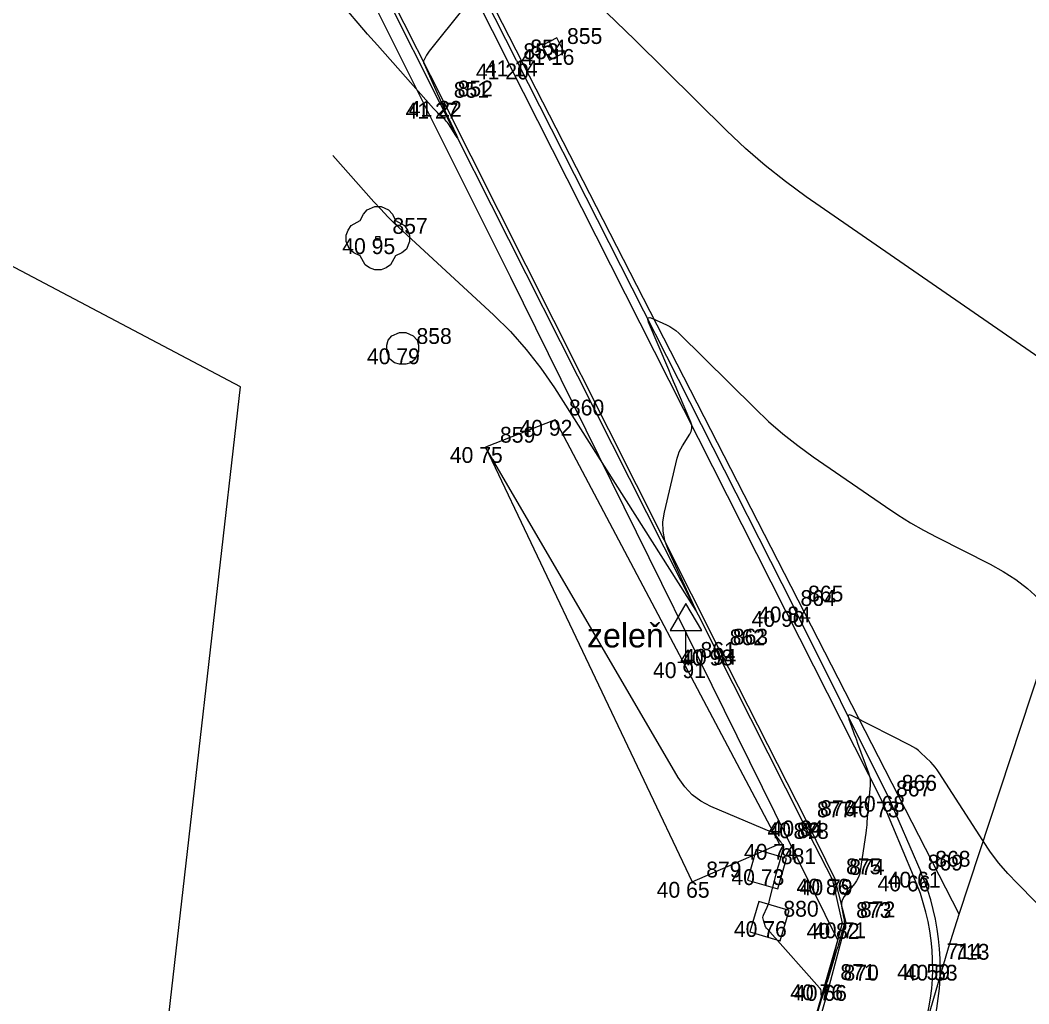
# Model space of a CAD drawing. Extents: x -702257 to -701487, y -1009871 to -1008841.
# Drawn here: x -701709.3 to -701693.36, y -1009123.07 to -1009107.52 of the extents above; entities that cross this region are included whole.
import ezdxf

# ---------------------------------------------------------------- set-up
doc = ezdxf.new("R2010")
doc.units = 0
for name, color, linetype in [('Ex_Major Contours', 7, 'Continuous'), ('Ex_Minor Contours', 7, 'Continuous'), ('Z_body', 7, 'Continuous'), ('Z_body_cisla', 7, 'Continuous'), ('Z_body_vysky_redukovane', 7, 'Continuous'), ('Z_dopravni_znacky', 7, 'Continuous'), ('Z_katastr_hranice', 7, 'Continuous'), ('Z_komunikace', 7, 'Continuous'), ('Z_obruba', 7, 'Continuous'), ('Z_popisy', 7, 'Continuous'), ('Z_site_kanalizace_znaky', 7, 'Continuous'), ('Z_site_nerozlisene_znaky', 7, 'Continuous'), ('Z_zelen_jednotliva', 7, 'Continuous'), ('Z_zelen_obvod', 7, 'Continuous')]:
    doc.layers.add(name, color=color, linetype=linetype)

# ---------------------------------------------------------------- blocks, each defined once
blk = doc.blocks.new('POINT_DISPLAY')
blk.add_line((0, 0), (0, 0))
blk = doc.blocks.new('Z620')
for p, q in [((-0.23, 0.13), (-0.17, 0.2)), ((-0.17, 0.2), (-0.05, 0.25)), ((-0.05, 0.25), (0.05, 0.25)), ((0.05, 0.25), (0.17, 0.2)), ((0.17, 0.2), (0.23, 0.13)), ((-0.25, 0.05), (-0.23, 0.13)), ((-0.25, -0.05), (-0.25, 0.05)), ((0.23, 0.13), (0.25, 0.05)), ((0.25, 0.05), (0.25, -0.05)), ((-0.2, -0.17), (-0.25, -0.05)), ((0.25, -0.05), (0.2, -0.17)), ((-0.13, -0.23), (-0.2, -0.17)), ((-0.05, -0.25), (-0.13, -0.23)), ((0.05, -0.25), (-0.05, -0.25)), ((0.13, -0.23), (0.05, -0.25)), ((0.2, -0.17), (0.13, -0.23))]:
    blk.add_line(p, q)
blk = doc.blocks.new('Z46260')
for p, q in [((0.13, 0.13), (-0.13, 0.13)), ((-0.13, 0.13), (-0.13, -0.13)), ((0.13, 0), (-0.13, 0)), ((0.13, -0.13), (0.13, 0.13)), ((-0.13, -0.13), (0.13, -0.13))]:
    blk.add_line(p, q)
blk = doc.blocks.new('Z24')
for p, q in [((-0.17, 0.45), (-0.05, 0.5)), ((-0.05, 0.5), (0.05, 0.5)), ((0.05, 0.5), (0.17, 0.45)), ((-0.28, 0.28), (-0.23, 0.38)), ((-0.23, 0.38), (-0.17, 0.45)), ((0.17, 0.45), (0.23, 0.38)), ((0.23, 0.38), (0.28, 0.28)), ((-0.47, 0.13), (-0.42, 0.2)), ((-0.42, 0.2), (-0.28, 0.28)), ((0.28, 0.28), (0.42, 0.2)), ((0.42, 0.2), (0.47, 0.13)), ((-0.5, 0.05), (-0.47, 0.13)), ((-0.5, -0.05), (-0.5, 0.05)), ((-0.03, -0.03), (-0.03, 0.03)), ((-0.03, 0.03), (0.03, 0.03)), ((0.03, 0.03), (0.03, -0.03)), ((0.47, 0.13), (0.5, 0.05)), ((0.5, 0.05), (0.5, -0.05)), ((-0.45, -0.17), (-0.5, -0.05)), ((0.03, -0.03), (-0.03, -0.03)), ((0.5, -0.05), (0.45, -0.17)), ((-0.38, -0.23), (-0.45, -0.17)), ((-0.28, -0.28), (-0.38, -0.23)), ((-0.2, -0.42), (-0.28, -0.28)), ((0.28, -0.28), (0.2, -0.42)), ((0.38, -0.23), (0.28, -0.28)), ((0.45, -0.17), (0.38, -0.23)), ((-0.13, -0.47), (-0.2, -0.42)), ((-0.05, -0.5), (-0.13, -0.47)), ((0.13, -0.47), (0.05, -0.5)), ((0.2, -0.42), (0.13, -0.47)), ((0.05, -0.5), (-0.05, -0.5))]:
    blk.add_line(p, q)
blk = doc.blocks.new('Z608')
for p, q in [((0.25, 0.25), (-0.25, 0.25)), ((-0.25, 0.25), (-0.25, -0.25)), ((0.25, -0.25), (0.25, 0.25)), ((-0.25, -0.25), (0.25, -0.25))]:
    blk.add_line(p, q)
blk = doc.blocks.new('Z527')
for p, q in [((0, 0.93), (-0.25, 0.5)), ((0.25, 0.5), (0, 0.93)), ((-0.25, 0.5), (0.25, 0.5)), ((0, 0), (0, 0.5)), ((-0.13, 0), (0.13, 0))]:
    blk.add_line(p, q)

msp = doc.modelspace()

# ---------------------------------------------------------------- linework, layer by layer
at = {"layer": 'Ex_Major Contours'}
msp.add_lwpolyline([(-701704.362, -1009109.662), (-701703.713, -1009110.392), (-701703.604, -1009110.513), (-701703.491, -1009110.63), (-701703.376, -1009110.745), (-701703.258, -1009110.856), (-701701.824, -1009112.18), (-701701.554, -1009112.445), (-701701.304, -1009112.726), (-701701.072, -1009113.023), (-701700.859, -1009113.335), (-701698.629, -1009116.845), (-701698.622, -1009116.856), (-701698.619, -1009116.859), (-701698.62, -1009116.854), (-701698.625, -1009116.842), (-701698.662, -1009116.763), (-701698.684, -1009116.716), (-701699.063, -1009115.89), (-701699.116, -1009115.746), (-701699.143, -1009115.599), (-701699.145, -1009115.45), (-701699.121, -1009115.298), (-701698.919, -1009114.447), (-701698.904, -1009114.395), (-701698.885, -1009114.345), (-701698.862, -1009114.297), (-701698.835, -1009114.25), (-701698.718, -1009114.068), (-701698.696, -1009114.022), (-701698.685, -1009113.975), (-701698.687, -1009113.926), (-701698.702, -1009113.877), (-701698.896, -1009113.42), (-701698.936, -1009113.328), (-701698.975, -1009113.235), (-701699.014, -1009113.142), (-701699.053, -1009113.049), (-701699.37, -1009112.298), (-701699.383, -1009112.252), (-701699.377, -1009112.227), (-701699.352, -1009112.222), (-701699.307, -1009112.237), (-701699.089, -1009112.336), (-701699.036, -1009112.362), (-701698.986, -1009112.394), (-701698.939, -1009112.429), (-701698.895, -1009112.469), (-701697.693, -1009113.657), (-701697.474, -1009113.864), (-701697.247, -1009114.06), (-701697.012, -1009114.247), (-701696.768, -1009114.424), (-701695.628, -1009115.211), (-701695.431, -1009115.342), (-701695.23, -1009115.467), (-701695.025, -1009115.584), (-701694.816, -1009115.694), (-701693.97, -1009116.121), (-701693.764, -1009116.235), (-701693.568, -1009116.363), (-701693.383, -1009116.506), (-701693.208, -1009116.664)], dxfattribs=at)
at = {"layer": 'Ex_Minor Contours'}
for points in [[(-701702.287, -1009107.325), (-701702.84, -1009108.014), (-701702.851, -1009108.029), (-701702.862, -1009108.045), (-701702.872, -1009108.06), (-701702.881, -1009108.077), (-701702.926, -1009108.159), (-701702.93, -1009108.167), (-701702.931, -1009108.176), (-701702.931, -1009108.184), (-701702.928, -1009108.193), (-701702.897, -1009108.262), (-701702.714, -1009108.675), (-701702.682, -1009108.746), (-701702.649, -1009108.818), (-701702.617, -1009108.889), (-701702.584, -1009108.96), (-701702.408, -1009109.343), (-701702.394, -1009109.374), (-701702.391, -1009109.386), (-701702.399, -1009109.377), (-701702.418, -1009109.348), (-701702.536, -1009109.164), (-701702.552, -1009109.141), (-701702.569, -1009109.119), (-701702.587, -1009109.098), (-701702.607, -1009109.078), (-701702.69, -1009109.002), (-701702.71, -1009108.983), (-701702.73, -1009108.963), (-701702.75, -1009108.942), (-701702.769, -1009108.922), (-701703.658, -1009107.921), (-701703.812, -1009107.746), (-701703.963, -1009107.569), (-701704.112, -1009107.391)], [(-701692.455, -1009113.369), (-701696.878, -1009110.313), (-701697.209, -1009110.073), (-701697.529, -1009109.82), (-701697.837, -1009109.553), (-701698.134, -1009109.272), (-701699.589, -1009107.834), (-701699.735, -1009107.691), (-701699.882, -1009107.548), (-701700.03, -1009107.406)], [(-701692.68, -1009122.038), (-701693.542, -1009121.168), (-701693.692, -1009121.009), (-701693.834, -1009120.842), (-701693.966, -1009120.668), (-701694.089, -1009120.486), (-701694.777, -1009119.417), (-701694.807, -1009119.372), (-701694.84, -1009119.33), (-701694.875, -1009119.29), (-701694.912, -1009119.251), (-701695.066, -1009119.101), (-701695.106, -1009119.065), (-701695.148, -1009119.033), (-701695.192, -1009119.004), (-701695.239, -1009118.978), (-701696.152, -1009118.517), (-701696.189, -1009118.503), (-701696.211, -1009118.507), (-701696.217, -1009118.528), (-701696.207, -1009118.567), (-701696.137, -1009118.756), (-701696.12, -1009118.804), (-701696.102, -1009118.851), (-701696.085, -1009118.898), (-701696.068, -1009118.946), (-701695.894, -1009119.419), (-701695.879, -1009119.468), (-701695.87, -1009119.517), (-701695.867, -1009119.567), (-701695.869, -1009119.618), (-701695.89, -1009119.836), (-701695.894, -1009119.88), (-701695.898, -1009119.925), (-701695.902, -1009119.969), (-701695.905, -1009120.013), (-701695.92, -1009120.191), (-701695.923, -1009120.236), (-701695.928, -1009120.28), (-701695.933, -1009120.324), (-701695.939, -1009120.368), (-701696.025, -1009120.967), (-701696.037, -1009121.023), (-701696.056, -1009121.075), (-701696.082, -1009121.125), (-701696.115, -1009121.171), (-701696.28, -1009121.372), (-701696.303, -1009121.407), (-701696.317, -1009121.445), (-701696.323, -1009121.484), (-701696.319, -1009121.526), (-701696.288, -1009121.698), (-701696.282, -1009121.741), (-701696.282, -1009121.783), (-701696.286, -1009121.825), (-701696.296, -1009121.868), (-701696.366, -1009122.11), (-701696.382, -1009122.164), (-701696.398, -1009122.219), (-701696.414, -1009122.273), (-701696.431, -1009122.327), (-701696.55, -1009122.717), (-701696.557, -1009122.739), (-701696.564, -1009122.761), (-701696.571, -1009122.783), (-701696.578, -1009122.805), (-701696.618, -1009122.931), (-701696.633, -1009122.977), (-701696.635, -1009122.982), (-701696.636, -1009122.983), (-701696.637, -1009122.981), (-701696.637, -1009122.976), (-701696.642, -1009122.877), (-701696.644, -1009122.859), (-701696.65, -1009122.842), (-701696.658, -1009122.827), (-701696.669, -1009122.812), (-701697.453, -1009121.93), (-701697.459, -1009121.924), (-701697.466, -1009121.917), (-701697.472, -1009121.911), (-701697.478, -1009121.904), (-701697.504, -1009121.878), (-701697.51, -1009121.871), (-701697.515, -1009121.864), (-701697.519, -1009121.856), (-701697.522, -1009121.848), (-701697.557, -1009121.744), (-701697.562, -1009121.724), (-701697.563, -1009121.704), (-701697.56, -1009121.684), (-701697.553, -1009121.665), (-701697.498, -1009121.541), (-701697.486, -1009121.514), (-701697.476, -1009121.486), (-701697.467, -1009121.458), (-701697.459, -1009121.429), (-701697.366, -1009121.058), (-701697.353, -1009121.011), (-701697.341, -1009120.963), (-701697.327, -1009120.916), (-701697.314, -1009120.869), (-701697.237, -1009120.605), (-701697.235, -1009120.596), (-701697.235, -1009120.586), (-701697.237, -1009120.577), (-701697.242, -1009120.569), (-701697.264, -1009120.534), (-701697.27, -1009120.526), (-701697.276, -1009120.518), (-701697.282, -1009120.509), (-701697.288, -1009120.501), (-701697.359, -1009120.408), (-701697.374, -1009120.391), (-701697.391, -1009120.376), (-701697.409, -1009120.363), (-701697.429, -1009120.353), (-701698.386, -1009119.947), (-701698.543, -1009119.865), (-701698.681, -1009119.763), (-701698.8, -1009119.639), (-701698.901, -1009119.493), (-701701.95, -1009114.27)]]:
    msp.add_lwpolyline(points, dxfattribs=at)
at = {"layer": 'Z_katastr_hranice'}
for p, q in [((-701694.46, -1009121.65), (-701719.83, -1009072.18)), ((-701701.55, -1009111.59), (-701721.16, -1009072.35)), ((-701694.46, -1009121.65), (-701689.61, -1009106.91)), ((-701705.82, -1009113.32), (-701716.36, -1009107.76)), ((-701696.38, -1009122.06), (-701701.55, -1009111.59)), ((-701708.43, -1009136.1), (-701705.82, -1009113.32)), ((-701694.63, -1009122.18), (-701694.46, -1009121.65)), ((-701703.95, -1009148.13), (-701696.38, -1009122.06)), ((-701708.88, -1009171.29), (-701694.63, -1009122.18))]:
    msp.add_line(p, q, dxfattribs=at)
at = {"layer": 'Z_komunikace'}
for p, q in [((-701701.46, -1009108.16), (-701704.86, -1009101.42)), ((-701701.46, -1009108.16), (-701697.08, -1009116.79)), ((-701695.59, -1009119.78), (-701697.08, -1009116.79)), ((-701695.59, -1009119.78), (-701695.07, -1009120.98))]:
    msp.add_line(p, q, dxfattribs=at)
msp.add_ellipse((-701698.479, -1009122.504), major_axis=(0.259, 3.78), ratio=0.981485, start_param=4.527221, end_param=5.193564, dxfattribs=at)
at = {"layer": 'Z_obruba'}
for p, q in [((-701704.97, -1009101.49), (-701701.58, -1009108.21)), ((-701702.67, -1009108.83), (-701706.13, -1009101.95)), ((-701706.09, -1009101.93), (-701702.62, -1009108.8)), ((-701697.2, -1009116.86), (-701701.58, -1009108.21)), ((-701698.31, -1009117.47), (-701702.67, -1009108.83)), ((-701702.62, -1009108.8), (-701698.26, -1009117.46)), ((-701697.2, -1009116.86), (-701695.68, -1009119.87)), ((-701696.93, -1009120.2), (-701698.31, -1009117.47)), ((-701698.26, -1009117.46), (-701696.88, -1009120.17)), ((-701695.68, -1009119.87), (-701695.19, -1009121.04)), ((-701696.47, -1009121.09), (-701696.93, -1009120.2)), ((-701696.88, -1009120.17), (-701696.42, -1009121.1)), ((-701696.47, -1009121.09), (-701696.31, -1009121.79)), ((-701696.25, -1009121.78), (-701696.42, -1009121.1)), ((-701696.31, -1009121.79), (-701696.57, -1009122.76)), ((-701696.51, -1009122.77), (-701696.25, -1009121.78)), ((-701698.84, -1009130.57), (-701696.57, -1009122.76)), ((-701696.51, -1009122.77), (-701698.79, -1009130.59))]:
    msp.add_line(p, q, dxfattribs=at)
msp.add_ellipse((-701698.37, -1009122.491), major_axis=(1.217, 3.285), ratio=0.995967, start_param=4.794436, end_param=5.493322, dxfattribs=at)
at = {"layer": 'Z_zelen_obvod'}
for p, q in [((-701700.85, -1009113.84), (-701701.95, -1009114.27)), ((-701697.3, -1009120.54), (-701700.85, -1009113.84)), ((-701701.95, -1009114.27), (-701698.68, -1009121.14)), ((-701698.68, -1009121.14), (-701697.3, -1009120.54))]:
    msp.add_line(p, q, dxfattribs=at)

# ---------------------------------------------------------------- block references
at = {"layer": 'Z_body'}
for p in [(-701700.88, -1009107.98), (-701701.58, -1009108.21), (-701701.46, -1009108.16), (-701702.67, -1009108.83), (-701702.62, -1009108.8), (-701703.65, -1009110.97), (-701703.26, -1009112.71), (-701700.85, -1009113.84), (-701701.95, -1009114.27), (-701697.08, -1009116.79), (-701697.2, -1009116.86), (-701698.31, -1009117.47), (-701698.26, -1009117.46), (-701698.78, -1009117.67), (-701695.68, -1009119.87), (-701695.59, -1009119.78), (-701696.93, -1009120.2), (-701696.88, -1009120.17), (-701697.3, -1009120.54), (-701697.5, -1009120.94), (-701695.07, -1009120.98), (-701698.68, -1009121.14), (-701696.47, -1009121.09), (-701696.42, -1009121.1), (-701695.19, -1009121.04), (-701697.46, -1009121.76), (-701696.31, -1009121.79), (-701696.25, -1009121.78), (-701694.88, -1009122.44), (-701694.76, -1009122.45), (-701696.57, -1009122.76), (-701696.51, -1009122.77)]:
    msp.add_blockref('POINT_DISPLAY', p, dxfattribs=at)
at = {"layer": 'Z_dopravni_znacky'}
msp.add_blockref('Z527', (-701698.78, -1009117.67), dxfattribs=at)
at = {"layer": 'Z_site_kanalizace_znaky', "rotation": -63.000000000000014}
msp.add_blockref('Z46260', (-701700.88, -1009107.98), dxfattribs=at)
at = {"layer": 'Z_site_kanalizace_znaky'}
msp.add_blockref('Z620', (-701703.26, -1009112.71), dxfattribs=at)
at = {"layer": 'Z_site_nerozlisene_znaky', "rotation": -16.200000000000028}
for p in [(-701697.5, -1009120.94), (-701697.46, -1009121.76)]:
    msp.add_blockref('Z608', p, dxfattribs=at)
at = {"layer": 'Z_zelen_jednotliva'}
msp.add_blockref('Z24', (-701703.65, -1009110.97), dxfattribs=at)

# ---------------------------------------------------------------- texts
at = {"layer": 'Z_body_cisla'}
for s, p in [('855', (-701700.66, -1009107.9)), ('853', (-701701.35, -1009108.14)), ('854', (-701701.24, -1009108.08)), ('851', (-701702.45, -1009108.75)), ('852', (-701702.39, -1009108.73)), ('857', (-701703.42, -1009110.9)), ('858', (-701703.04, -1009112.64)), ('860', (-701700.63, -1009113.77)), ('859', (-701701.72, -1009114.2)), ('864', (-701696.97, -1009116.78)), ('865', (-701696.85, -1009116.71)), ('862', (-701698.09, -1009117.4)), ('863', (-701698.04, -1009117.39)), ('861', (-701698.55, -1009117.6)), ('867', (-701695.46, -1009119.79)), ('866', (-701695.37, -1009119.7)), ('877', (-701696.71, -1009120.12)), ('876', (-701696.66, -1009120.1)), ('878', (-701697.08, -1009120.46)), ('881', (-701697.28, -1009120.86)), ('868', (-701694.84, -1009120.9)), ('879', (-701698.46, -1009121.07)), ('875', (-701696.25, -1009121.02)), ('874', (-701696.2, -1009121.03)), ('869', (-701694.96, -1009120.96)), ('880', (-701697.24, -1009121.69)), ('873', (-701696.09, -1009121.71)), ('872', (-701696.03, -1009121.7)), ('714', (-701694.66, -1009122.36)), ('713', (-701694.54, -1009122.37)), ('871', (-701696.34, -1009122.69)), ('870', (-701696.29, -1009122.7))]:
    msp.add_text(s, height=0.25, dxfattribs=at).set_placement(p)
at = {"layer": 'Z_body_vysky_redukovane'}
for s, p in [('41 16', (-701701.38, -1009108.23)), ('41 20', (-701702.101, -1009108.46)), ('41 14', (-701701.96, -1009108.41)), ('41 27', (-701703.212, -1009109.08)), ('41 22', (-701703.162, -1009109.05)), ('40 95', (-701704.213, -1009111.22)), ('40 79', (-701703.823, -1009112.96)), ('40 92', (-701701.412, -1009114.09)), ('40 75', (-701702.513, -1009114.52)), ('40 84', (-701697.643, -1009117.04)), ('40 90', (-701697.742, -1009117.11)), ('40 98', (-701698.873, -1009117.72)), ('40 94', (-701698.823, -1009117.71)), ('40 91', (-701699.301, -1009117.92)), ('40 73', (-701696.243, -1009120.12)), ('40 68', (-701696.153, -1009120.03)), ('40 89', (-701697.493, -1009120.45)), ('40 84', (-701697.443, -1009120.42)), ('40 74', (-701697.863, -1009120.79)), ('40 73', (-701698.062, -1009121.19)), ('40 61', (-701695.591, -1009121.23)), ('40 65', (-701699.243, -1009121.39)), ('40 86', (-701697.033, -1009121.34)), ('40 79', (-701696.983, -1009121.35)), ('40 66', (-701695.752, -1009121.29)), ('40 76', (-701698.023, -1009122.01)), ('40 82', (-701696.873, -1009122.04)), ('40 71', (-701696.771, -1009122.03)), ('40 59', (-701695.443, -1009122.69)), ('40 53', (-701695.323, -1009122.7)), ('40 76', (-701697.132, -1009123.01)), ('40 66', (-701697.073, -1009123.02))]:
    msp.add_text(s, height=0.25, dxfattribs=at).set_placement(p)
at = {"layer": 'Z_popisy'}
msp.add_text('zeleň', height=0.38, dxfattribs=at).set_placement((-701700.345, -1009117.436))

doc.saveas('drawing.dxf')
